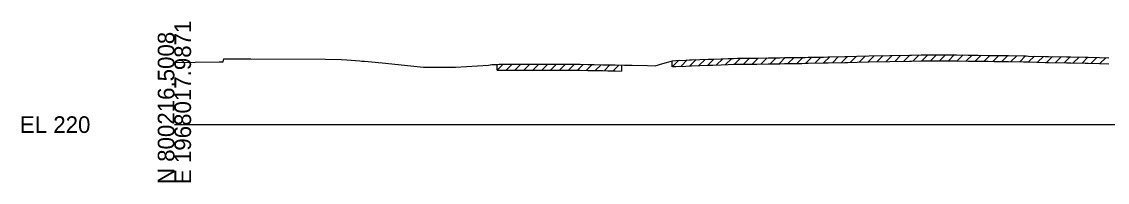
# Model space of a CAD drawing. Extents: x -119 to 6018, y -82 to 34226.
# Drawn here: x -25.7 to 157, y 31490.3 to 31517.3 of the extents above; entities that cross this region are included whole.
import ezdxf

# ---------------------------------------------------------------- set-up
doc = ezdxf.new("R2010")
doc.units = 0
for name, color, linetype in [('Default', 7, 'Continuous'), ('RD_GPK_XS_Cell', 7, 'Continuous'), ('RD_XS_ExGround', 7, 'Continuous'), ('RD_XS_ExPaveRet', 7, 'Continuous')]:
    doc.layers.add(name, color=color, linetype=linetype)

msp = doc.modelspace()

# ---------------------------------------------------------------- linework, layer by layer
at = {"layer": 'RD_GPK_XS_Cell'}
msp.add_line((0, 31500), (300, 31500), dxfattribs=at)
at = {"layer": 'RD_XS_ExGround'}
msp.add_lwpolyline([(0, 31510.47), (3.48, 31510.49), (7.55, 31510.57), (8.2, 31510.58), (8.31, 31511.08), (8.95, 31511.08), (10.64, 31511.07), (11.59, 31511.07), (12.84, 31511.06), (25.42, 31511.02), (28.13, 31510.95), (29.03, 31510.9), (31.21, 31510.71), (31.53, 31510.69), (32.01, 31510.67), (34.95, 31510.38), (41.9, 31509.64), (47.3, 31509.66), (52.88, 31510), (53.45, 31510.09), (54.18, 31510.12), (54.66, 31510.15), (56.11, 31510.15), (57.18, 31510.16), (59.47, 31510.17), (60.82, 31510.18), (62.84, 31510.18), (63.67, 31510.18), (64.5, 31510.18), (65.59, 31510.18), (67.17, 31510.16), (68.27, 31510.14), (69.57, 31510.12), (70.67, 31510.1), (72.03, 31510.08), (72.95, 31510.06), (74.18, 31510.03), (75.77, 31510), (76.21, 31509.99), (77.04, 31509.98), (79.63, 31509.94), (80.91, 31509.89), (82.19, 31510.27), (83.82, 31510.75), (84.4, 31510.79), (84.97, 31510.82), (85.45, 31510.8), (86.69, 31510.89), (87, 31510.9), (89.81, 31510.99), (90.16, 31511), (90.6, 31511.02), (92.03, 31511.06), (93.19, 31511.11), (94.12, 31511.14), (94.78, 31511.16), (96.56, 31511.18), (98.03, 31511.19), (99.93, 31511.21), (100.8, 31511.22), (101.89, 31511.24), (102.68, 31511.26), (103.3, 31511.27), (105.58, 31511.3), (106.14, 31511.31), (106.65, 31511.32), (109.23, 31511.37), (110, 31511.39), (112.81, 31511.45), (113.31, 31511.47), (114.93, 31511.51), (116.86, 31511.57), (120.41, 31511.63), (123.69, 31511.68), (124.03, 31511.68), (125.67, 31511.71), (126.87, 31511.73), (127.97, 31511.74), (129.11, 31511.75), (130.27, 31511.74), (131.64, 31511.72), (133.61, 31511.69), (134.47, 31511.68), (135.27, 31511.67), (136.97, 31511.65), (137.95, 31511.64), (139.18, 31511.62), (139.85, 31511.61), (140.38, 31511.6), (142.88, 31511.55), (143.33, 31511.54), (143.74, 31511.53), (146.55, 31511.47), (147.09, 31511.46), (150.14, 31511.4), (150.45, 31511.4), (150.86, 31511.39), (153.29, 31511.35), (153.79, 31511.33), (155.67, 31511.27), (157.26, 31511.23)], dxfattribs=at)
at = {"layer": 'RD_XS_ExPaveRet'}
for p, q in [((83.76, 31509.74), (84.84, 31510.81)), ((83.76, 31509.74), (83.76, 31510.74)), ((85.26, 31509.81), (86.32, 31510.87)), ((86.76, 31509.9), (87.8, 31510.93)), ((88.26, 31509.94), (89.3, 31510.97)), ((89.76, 31509.99), (90.8, 31511.02)), ((91.26, 31510.04), (92.3, 31511.07)), ((92.76, 31510.09), (93.81, 31511.13)), ((94.26, 31510.15), (95.28, 31511.17)), ((95.76, 31510.17), (96.78, 31511.18)), ((97.26, 31510.18), (98.27, 31511.19)), ((98.76, 31510.2), (99.78, 31511.21)), ((100.26, 31510.21), (101.28, 31511.23)), ((101.76, 31510.24), (102.78, 31511.26)), ((103.26, 31510.27), (104.28, 31511.28)), ((104.76, 31510.29), (105.78, 31511.31)), ((106.26, 31510.31), (107.28, 31511.33)), ((107.76, 31510.34), (108.78, 31511.36)), ((109.26, 31510.37), (110.29, 31511.39)), ((110, 31510.39), (112.81, 31510.45)), ((110.76, 31510.4), (111.79, 31511.43)), ((112.26, 31510.44), (113.29, 31511.46)), ((112.81, 31510.45), (113.31, 31510.47)), ((113.31, 31510.47), (114.93, 31510.51)), ((113.76, 31510.48), (114.79, 31511.51)), ((114.93, 31510.51), (116.86, 31510.57)), ((115.26, 31510.52), (116.3, 31511.55)), ((116.76, 31510.56), (117.78, 31511.58)), ((116.86, 31510.57), (120.41, 31510.63)), ((118.26, 31510.59), (119.28, 31511.61)), ((119.76, 31510.62), (120.78, 31511.63)), ((120.41, 31510.63), (123.69, 31510.68)), ((121.26, 31510.64), (122.28, 31511.66)), ((122.76, 31510.66), (123.78, 31511.68)), ((123.69, 31510.68), (124.03, 31510.68)), ((124.03, 31510.68), (125.67, 31510.71)), ((124.26, 31510.69), (125.28, 31511.7)), ((125.67, 31510.71), (126.87, 31510.73)), ((125.76, 31510.71), (126.78, 31511.73)), ((126.87, 31510.73), (127.97, 31510.74)), ((127.26, 31510.73), (128.28, 31511.75)), ((127.97, 31510.74), (129.11, 31510.75)), ((128.76, 31510.75), (129.76, 31511.75)), ((129.11, 31510.75), (130.27, 31510.74)), ((130.26, 31510.74), (131.25, 31511.73)), ((130.27, 31510.74), (131.64, 31510.72)), ((131.64, 31510.72), (133.61, 31510.69)), ((131.76, 31510.72), (132.75, 31511.71)), ((133.26, 31510.7), (134.25, 31511.68)), ((133.61, 31510.69), (134.47, 31510.68)), ((134.47, 31510.68), (135.27, 31510.67)), ((134.76, 31510.68), (135.75, 31511.66)), ((135.27, 31510.67), (136.97, 31510.65)), ((136.26, 31510.66), (137.25, 31511.65)), ((136.97, 31510.65), (137.95, 31510.64)), ((137.76, 31510.64), (138.75, 31511.63)), ((137.95, 31510.64), (139.18, 31510.62)), ((139.18, 31510.62), (139.85, 31510.61)), ((139.26, 31510.62), (140.25, 31511.61)), ((139.85, 31510.61), (140.38, 31510.6)), ((140.38, 31510.6), (142.88, 31510.55)), ((140.76, 31510.6), (141.75, 31511.58)), ((142.26, 31510.57), (143.24, 31511.55)), ((142.88, 31510.55), (143.33, 31510.54)), ((143.33, 31510.54), (143.74, 31510.53)), ((143.74, 31510.53), (146.55, 31510.47)), ((143.76, 31510.53), (144.74, 31511.51)), ((145.26, 31510.5), (146.24, 31511.48)), ((146.55, 31510.47), (147.09, 31510.46)), ((146.76, 31510.47), (147.75, 31511.45)), ((147.09, 31510.46), (150.14, 31510.4)), ((148.26, 31510.44), (149.25, 31511.42)), ((149.76, 31510.41), (150.75, 31511.39)), ((151.26, 31510.38), (152.25, 31511.37)), ((152.76, 31510.36), (153.74, 31511.33)), ((154.26, 31510.31), (155.24, 31511.28)), ((155.76, 31510.27), (156.74, 31511.24)), ((54.32, 31509.13), (55.34, 31510.15)), ((54.32, 31509.13), (54.32, 31510.13)), ((54.32, 31509.13), (54.66, 31509.15)), ((54.66, 31509.15), (56.11, 31509.15)), ((55.82, 31509.15), (56.83, 31510.15)), ((56.11, 31509.15), (57.18, 31509.16)), ((57.18, 31509.16), (59.47, 31509.17)), ((57.32, 31509.16), (58.33, 31510.16)), ((58.82, 31509.17), (59.83, 31510.17)), ((59.47, 31509.17), (60.82, 31509.18)), ((60.32, 31509.17), (61.32, 31510.18)), ((60.82, 31509.18), (62.84, 31509.18)), ((61.82, 31509.18), (62.82, 31510.18)), ((62.84, 31509.18), (63.67, 31509.18)), ((63.32, 31509.18), (64.32, 31510.18)), ((63.67, 31509.18), (64.5, 31509.18)), ((64.5, 31509.18), (65.59, 31509.18)), ((64.82, 31509.18), (65.82, 31510.17)), ((65.59, 31509.18), (67.17, 31509.16)), ((66.32, 31509.17), (67.31, 31510.16)), ((67.17, 31509.16), (68.27, 31509.14)), ((67.82, 31509.15), (68.8, 31510.13)), ((68.27, 31509.14), (69.57, 31509.12)), ((69.32, 31509.12), (70.3, 31510.11)), ((69.57, 31509.12), (70.67, 31509.1)), ((70.67, 31509.1), (72.03, 31509.08)), ((70.82, 31509.1), (71.8, 31510.08)), ((72.03, 31509.08), (72.95, 31509.06)), ((72.32, 31509.07), (73.3, 31510.05)), ((72.95, 31509.06), (74.18, 31509.03)), ((73.82, 31509.04), (74.8, 31510.02)), ((74.18, 31509.03), (75.26, 31509.01)), ((75.26, 31510.01), (75.26, 31509.01)), ((83.76, 31509.74), (83.82, 31509.75)), ((83.82, 31509.75), (84.4, 31509.79)), ((84.4, 31509.79), (84.97, 31509.82)), ((84.97, 31509.82), (85.45, 31509.8)), ((85.45, 31509.8), (86.69, 31509.89)), ((86.69, 31509.89), (87, 31509.9)), ((87, 31509.9), (89.81, 31509.99)), ((89.81, 31509.99), (90.16, 31510)), ((90.16, 31510), (90.6, 31510.02)), ((90.6, 31510.02), (92.03, 31510.06)), ((92.03, 31510.06), (93.19, 31510.11)), ((93.19, 31510.11), (94.12, 31510.14)), ((94.12, 31510.14), (94.78, 31510.16)), ((94.78, 31510.16), (96.56, 31510.18)), ((96.56, 31510.18), (98.03, 31510.19)), ((98.03, 31510.19), (99.93, 31510.21)), ((99.93, 31510.21), (100.8, 31510.22)), ((100.8, 31510.22), (101.89, 31510.24)), ((101.89, 31510.24), (102.68, 31510.26)), ((102.68, 31510.26), (103.3, 31510.27)), ((103.3, 31510.27), (105.58, 31510.3)), ((105.58, 31510.3), (106.14, 31510.31)), ((106.14, 31510.31), (106.65, 31510.32)), ((106.65, 31510.32), (109.23, 31510.37)), ((109.23, 31510.37), (110, 31510.39)), ((150.14, 31510.4), (150.45, 31510.4)), ((150.45, 31510.4), (150.86, 31510.39)), ((150.86, 31510.39), (153.29, 31510.35)), ((153.29, 31510.35), (153.79, 31510.33)), ((153.79, 31510.33), (155.67, 31510.27)), ((155.67, 31510.27), (157.26, 31510.23))]:
    msp.add_line(p, q, dxfattribs=at)

# ---------------------------------------------------------------- texts
at = {"layer": 'Default'}
msp.add_text('-', height=0.0001, dxfattribs=at).set_placement((0, 31500))
at = {"layer": 'RD_GPK_XS_Cell'}
for s, p in [('E 1968017.9871', (2.8, 31490)), ('N 800216.5008', (0, 31490))]:
    msp.add_text(s, height=2.8, rotation=90, dxfattribs=at).set_placement(p)
msp.add_text('EL 220', height=2.8, dxfattribs=at).set_placement((-26, 31498.6))

doc.saveas('drawing.dxf')
